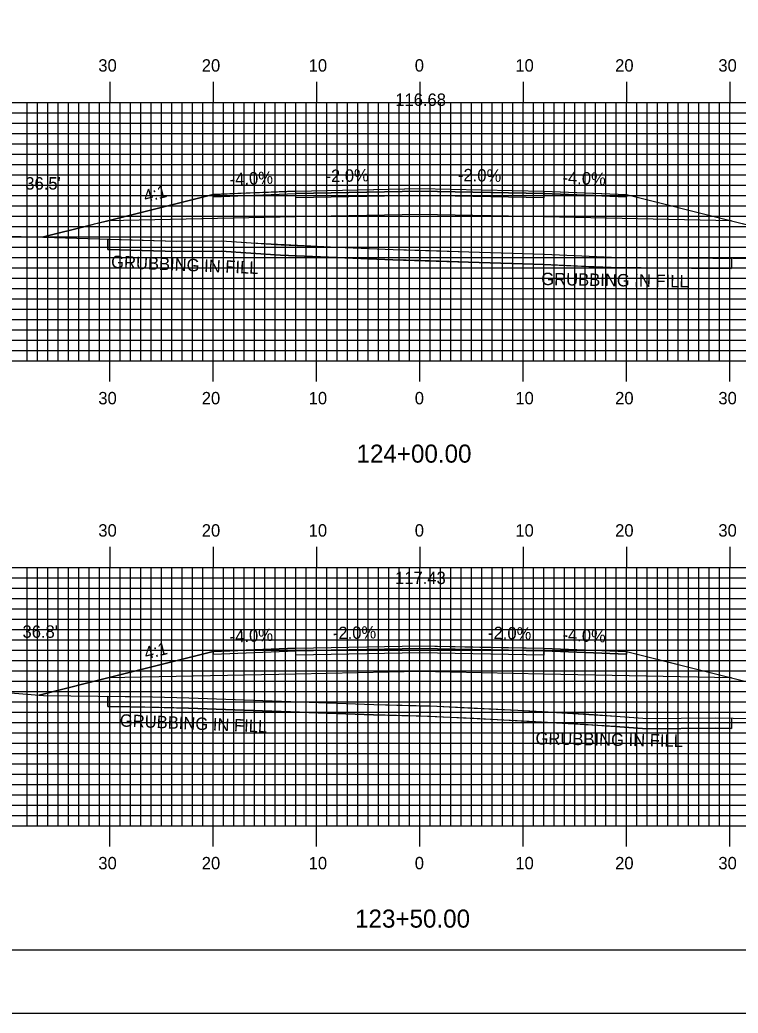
# Model space of a CAD drawing. Extents: x 1772809 to 1773153, y 442591 to 442811.
# Drawn here: x 1772936.4 to 1773005.9, y 442590.5 to 442686.7 of the extents above; entities that cross this region are included whole.
import ezdxf

# ---------------------------------------------------------------- set-up
doc = ezdxf.new("R2010")
doc.units = 0
for name, color, linetype in [('ANNOTATION', 7, 'Continuous'), ('BORDER', 7, 'Continuous'), ('D_Roadway_Centerline', 7, 'Continuous'), ('D_Roadway_Centerline_Text', 7, 'Continuous'), ('D_Roadway_Edge_Shoulder', 7, 'Continuous'), ('D_Roadway_Edge_TW', 7, 'Continuous'), ('D_Roadway_Pavement', 7, 'Continuous'), ('D_Roadway_SlopeLines', 7, 'Continuous'), ('D_Roadway_SubGrade', 7, 'Continuous'), ('D_Text_Standard', 7, 'Continuous'), ('GRUBBING IN FILL', 7, 'Continuous'), ('H_V ANNOTATION', 7, 'Continuous'), ('MAJOR', 7, 'Continuous'), ('MINOR', 7, 'Continuous'), ('PLOT BOUNDARY', 7, 'Continuous'), ('S_Roadway_Centerline', 7, 'Continuous')]:
    doc.layers.add(name, color=color, linetype=linetype)

msp = doc.modelspace()

# ---------------------------------------------------------------- linework, layer by layer
at = {"layer": 'BORDER'}
msp.add_lwpolyline([(1772825.52, 442596.665), (1773145.52, 442596.665), (1773145.52, 442806.665), (1772825.52, 442806.665)], close=True, dxfattribs=at)
at = {"layer": 'D_Roadway_Centerline'}
for points in [[(1772938.572, 442665.647), (1772943.119, 442666.784), (1772943.663, 442666.92), (1772944.946, 442667.24), (1772955.12, 442669.784), (1772957.831, 442669.893), (1772963.119, 442670.104), (1772973.69, 442670.316), (1772975.12, 442670.344), (1772987.119, 442670.104), (1772991.874, 442669.914), (1772995.12, 442669.784), (1773005.294, 442667.24), (1773009.361, 442666.224), (1773020.862, 442663.348)], [(1772938.304, 442621.329), (1772943.12, 442622.534), (1772944.93, 442622.986), (1772944.946, 442622.99), (1772945.075, 442623.022), (1772955.12, 442625.534), (1772963.12, 442625.854), (1772975.12, 442626.094), (1772980.946, 442625.978), (1772987.12, 442625.854), (1772995.119, 442625.534), (1773000.632, 442624.156), (1773005.293, 442622.99), (1773023.945, 442618.327)]]:
    msp.add_lwpolyline(points, dxfattribs=at)
at = {"layer": 'D_Roadway_Edge_Shoulder'}
for points in [[(1772963.119, 442670.104), (1772955.12, 442669.784), (1772955.12, 442669.534), (1772963.119, 442669.854)], [(1772987.119, 442670.104), (1772995.12, 442669.784), (1772995.12, 442669.534), (1772987.119, 442669.854)], [(1772963.12, 442625.854), (1772955.12, 442625.534), (1772955.12, 442625.284), (1772963.12, 442625.604)], [(1772987.12, 442625.854), (1772995.119, 442625.534), (1772995.119, 442625.284), (1772987.12, 442625.604)]]:
    msp.add_lwpolyline(points, close=True, dxfattribs=at)
at = {"layer": 'D_Roadway_Edge_TW'}
for points in [[(1772963.119, 442669.854), (1772963.119, 442670.104), (1772975.12, 442670.344), (1772987.119, 442670.104), (1772987.119, 442669.854), (1772975.12, 442670.094)], [(1772963.12, 442625.604), (1772963.12, 442625.854), (1772975.12, 442626.094), (1772987.12, 442625.854), (1772987.12, 442625.604), (1772975.12, 442625.844)]]:
    msp.add_lwpolyline(points, close=True, dxfattribs=at)
at = {"layer": 'D_Roadway_Pavement'}
for points in [[(1772963.119, 442669.437), (1772963.119, 442669.854), (1772975.12, 442670.094), (1772987.119, 442669.854), (1772987.119, 442669.437), (1772975.12, 442669.677)], [(1772963.12, 442625.187), (1772963.12, 442625.604), (1772975.12, 442625.844), (1772987.12, 442625.604), (1772987.12, 442625.187), (1772975.12, 442625.427)]]:
    msp.add_lwpolyline(points, close=True, dxfattribs=at)
at = {"layer": 'D_Roadway_SlopeLines'}
for points in [[(1772955.12, 442669.784), (1772944.946, 442667.24), (1772943.119, 442666.784), (1772938.572, 442665.647)], [(1772995.12, 442669.784), (1773005.294, 442667.24), (1773020.862, 442663.348)], [(1772955.12, 442625.534), (1772944.946, 442622.99), (1772943.12, 442622.534), (1772938.304, 442621.329)], [(1772995.119, 442625.534), (1773005.293, 442622.99), (1773023.945, 442618.327)]]:
    msp.add_lwpolyline(points, dxfattribs=at)
at = {"layer": 'D_Roadway_SubGrade'}
for points in [[(1772963.119, 442667.604), (1772944.946, 442667.24), (1772955.12, 442669.784), (1772955.12, 442669.534), (1772963.119, 442669.854), (1772975.12, 442670.094), (1772987.119, 442669.854), (1772995.12, 442669.534), (1772995.12, 442669.784), (1773005.294, 442667.24), (1772987.119, 442667.604), (1772975.12, 442667.844)], [(1772963.12, 442623.354), (1772944.946, 442622.99), (1772955.12, 442625.534), (1772955.12, 442625.284), (1772963.12, 442625.604), (1772975.12, 442625.844), (1772987.12, 442625.604), (1772995.119, 442625.284), (1772995.119, 442625.534), (1773005.293, 442622.99), (1772987.12, 442623.354), (1772975.12, 442623.594)]]:
    msp.add_lwpolyline(points, close=True, dxfattribs=at)
at = {"layer": 'GRUBBING IN FILL'}
for p, q in [((1772944.946, 442665.449), (1772944.946, 442664.448)), ((1772944.946, 442665.449), (1772944.946, 442664.448)), ((1773005.294, 442663.615), (1773005.294, 442662.615)), ((1773005.294, 442663.615), (1773005.294, 442662.615)), ((1772944.946, 442621.214), (1772944.946, 442620.214)), ((1772944.946, 442621.214), (1772944.946, 442620.214)), ((1773005.293, 442619.099), (1773005.293, 442618.099)), ((1773005.293, 442619.099), (1773005.293, 442618.099))]:
    msp.add_line(p, q, dxfattribs=at)
for points in [[(1772944.946, 442665.449), (1772951.585, 442665.243), (1772955.937, 442665.302), (1772958.821, 442665.109), (1772967.126, 442664.689), (1772972.546, 442664.462), (1772975.12, 442664.38), (1772975.12, 442663.38), (1772972.509, 442663.462), (1772967.08, 442663.69), (1772961.651, 442663.917), (1772955.91, 442664.301), (1772953.743, 442664.272), (1772951.576, 442664.242), (1772948.261, 442664.345), (1772944.946, 442664.448)], [(1772944.946, 442665.449), (1772951.585, 442665.243), (1772955.937, 442665.302), (1772958.821, 442665.109), (1772967.126, 442664.689), (1772972.546, 442664.462), (1772975.12, 442664.38), (1772975.12, 442663.38), (1772972.509, 442663.462), (1772967.08, 442663.69), (1772961.651, 442663.917), (1772955.91, 442664.301), (1772953.743, 442664.272), (1772951.576, 442664.242), (1772948.261, 442664.345), (1772944.946, 442664.448)], [(1772975.12, 442664.38), (1772979.865, 442664.231), (1772987.185, 442663.999), (1772993.671, 442663.693), (1773003.491, 442663.627), (1773005.294, 442663.615), (1773005.294, 442662.615), (1772999.469, 442662.654), (1772993.644, 442662.693), (1772990.395, 442662.847), (1772987.145, 442663), (1772979.827, 442663.231), (1772975.12, 442663.38)], [(1772975.12, 442664.38), (1772979.865, 442664.231), (1772987.185, 442663.999), (1772993.671, 442663.693), (1773003.491, 442663.627), (1773005.294, 442663.615), (1773005.294, 442662.615), (1772999.469, 442662.654), (1772993.644, 442662.693), (1772990.395, 442662.847), (1772987.145, 442663), (1772979.827, 442663.231), (1772975.12, 442663.38)], [(1772944.946, 442621.214), (1772949.251, 442621.157), (1772952.79, 442621.064), (1772961.732, 442620.742), (1772970.673, 442620.42), (1772975.12, 442620.302), (1772975.12, 442619.302), (1772970.642, 442619.421), (1772961.7, 442619.742), (1772952.758, 442620.064), (1772947.088, 442620.186), (1772944.946, 442620.214)], [(1772944.946, 442621.214), (1772949.251, 442621.157), (1772952.79, 442621.064), (1772961.732, 442620.742), (1772970.673, 442620.42), (1772975.12, 442620.302), (1772975.12, 442619.302), (1772970.642, 442619.421), (1772961.7, 442619.742), (1772952.758, 442620.064), (1772947.088, 442620.186), (1772944.946, 442620.214)], [(1772975.12, 442620.302), (1772976.166, 442620.275), (1772980.387, 442620.063), (1772984.607, 442619.852), (1772987.835, 442619.679), (1772994.102, 442619.289), (1772997.141, 442619.072), (1773003.711, 442619.13), (1773005.293, 442619.099), (1773005.293, 442618.099), (1773003.706, 442618.13), (1773000.408, 442618.101), (1772997.109, 442618.072), (1772994.055, 442618.29), (1772980.342, 442619.064), (1772975.12, 442619.302)], [(1772975.12, 442620.302), (1772976.166, 442620.275), (1772980.387, 442620.063), (1772984.607, 442619.852), (1772987.835, 442619.679), (1772994.102, 442619.289), (1772997.141, 442619.072), (1773003.711, 442619.13), (1773005.293, 442619.099), (1773005.293, 442618.099), (1773003.706, 442618.13), (1773000.408, 442618.101), (1772997.109, 442618.072), (1772994.055, 442618.29), (1772980.342, 442619.064), (1772975.12, 442619.302)]]:
    msp.add_lwpolyline(points, close=True, dxfattribs=at)
for points in [[(1772944.946, 442664.448), (1772951.576, 442664.242), (1772955.91, 442664.301), (1772961.651, 442663.917), (1772972.509, 442663.462), (1772987.145, 442663), (1772993.644, 442662.693), (1773005.294, 442662.615)], [(1772944.946, 442664.448), (1772951.576, 442664.242), (1772955.91, 442664.301), (1772961.651, 442663.917), (1772972.509, 442663.462), (1772987.145, 442663), (1772993.644, 442662.693), (1773005.294, 442662.615)], [(1772944.946, 442620.214), (1772949.231, 442620.158), (1772952.758, 442620.064), (1772970.642, 442619.421), (1772976.128, 442619.275), (1772984.555, 442618.853), (1772991, 442618.508), (1772997.109, 442618.072), (1773003.706, 442618.13), (1773005.293, 442618.099)], [(1772944.946, 442620.214), (1772949.231, 442620.158), (1772952.758, 442620.064), (1772970.642, 442619.421), (1772976.128, 442619.275), (1772984.555, 442618.853), (1772991, 442618.508), (1772997.109, 442618.072), (1773003.706, 442618.13), (1773005.293, 442618.099)]]:
    msp.add_lwpolyline(points, dxfattribs=at)
at = {"layer": 'MAJOR'}
for p, q in [((1772945.12, 442680.669), (1772945.12, 442678.665)), ((1772955.12, 442680.669), (1772955.12, 442678.665)), ((1772965.12, 442680.669), (1772965.12, 442678.665)), ((1772975.12, 442680.669), (1772975.12, 442678.665)), ((1772985.12, 442680.669), (1772985.12, 442678.665)), ((1772995.12, 442680.669), (1772995.12, 442678.665)), ((1773005.12, 442680.669), (1773005.12, 442678.665)), ((1772835.12, 442678.665), (1773115.12, 442678.665)), ((1772835.12, 442678.665), (1773115.12, 442678.665)), ((1772945.12, 442653.665), (1772945.12, 442678.665)), ((1772955.12, 442653.665), (1772955.12, 442678.665)), ((1772965.12, 442653.665), (1772965.12, 442678.665)), ((1772975.12, 442653.665), (1772975.12, 442678.665)), ((1772985.12, 442653.665), (1772985.12, 442678.665)), ((1772995.12, 442653.665), (1772995.12, 442678.665)), ((1773005.12, 442653.665), (1773005.12, 442678.665)), ((1772835.12, 442673.665), (1773115.12, 442673.665)), ((1772835.12, 442668.665), (1773115.12, 442668.665)), ((1772835.12, 442663.665), (1773115.12, 442663.665)), ((1772835.12, 442658.665), (1773115.12, 442658.665)), ((1772835.12, 442653.665), (1773115.12, 442653.665)), ((1772835.12, 442653.665), (1773115.12, 442653.665)), ((1772945.12, 442651.661), (1772945.12, 442653.665)), ((1772955.12, 442651.661), (1772955.12, 442653.665)), ((1772965.12, 442651.661), (1772965.12, 442653.665)), ((1772975.12, 442651.661), (1772975.12, 442653.665)), ((1772985.12, 442651.661), (1772985.12, 442653.665)), ((1772995.12, 442651.661), (1772995.12, 442653.665)), ((1773005.12, 442651.661), (1773005.12, 442653.665)), ((1772945.12, 442635.669), (1772945.12, 442633.665)), ((1772955.12, 442635.669), (1772955.12, 442633.665)), ((1772965.12, 442635.669), (1772965.12, 442633.665)), ((1772975.12, 442635.669), (1772975.12, 442633.665)), ((1772985.12, 442635.669), (1772985.12, 442633.665)), ((1772995.12, 442635.669), (1772995.12, 442633.665)), ((1773005.12, 442635.669), (1773005.12, 442633.665)), ((1772835.12, 442633.665), (1773115.12, 442633.665)), ((1772835.12, 442633.665), (1773115.12, 442633.665)), ((1772945.12, 442608.665), (1772945.12, 442633.665)), ((1772955.12, 442608.665), (1772955.12, 442633.665)), ((1772965.12, 442608.665), (1772965.12, 442633.665)), ((1772975.12, 442608.665), (1772975.12, 442633.665)), ((1772985.12, 442608.665), (1772985.12, 442633.665)), ((1772995.12, 442608.665), (1772995.12, 442633.665)), ((1773005.12, 442608.665), (1773005.12, 442633.665)), ((1772835.12, 442628.665), (1773115.12, 442628.665)), ((1772835.12, 442623.665), (1773115.12, 442623.665)), ((1772835.12, 442618.665), (1773115.12, 442618.665)), ((1772835.12, 442613.665), (1773115.12, 442613.665)), ((1772835.12, 442608.665), (1773115.12, 442608.665)), ((1772835.12, 442608.665), (1773115.12, 442608.665)), ((1772945.12, 442606.661), (1772945.12, 442608.665)), ((1772955.12, 442606.661), (1772955.12, 442608.665)), ((1772965.12, 442606.661), (1772965.12, 442608.665)), ((1772975.12, 442606.661), (1772975.12, 442608.665)), ((1772985.12, 442606.661), (1772985.12, 442608.665)), ((1772995.12, 442606.661), (1772995.12, 442608.665)), ((1773005.12, 442606.661), (1773005.12, 442608.665))]:
    msp.add_line(p, q, dxfattribs=at)
at = {"layer": 'MINOR'}
for p, q in [((1772937.12, 442653.665), (1772937.12, 442678.665)), ((1772938.12, 442653.665), (1772938.12, 442678.665)), ((1772939.12, 442653.665), (1772939.12, 442678.665)), ((1772940.12, 442653.665), (1772940.12, 442678.665)), ((1772941.12, 442653.665), (1772941.12, 442678.665)), ((1772942.12, 442653.665), (1772942.12, 442678.665)), ((1772943.12, 442653.665), (1772943.12, 442678.665)), ((1772944.12, 442653.665), (1772944.12, 442678.665)), ((1772946.12, 442653.665), (1772946.12, 442678.665)), ((1772947.12, 442653.665), (1772947.12, 442678.665)), ((1772948.12, 442653.665), (1772948.12, 442678.665)), ((1772949.12, 442653.665), (1772949.12, 442678.665)), ((1772950.12, 442653.665), (1772950.12, 442678.665)), ((1772951.12, 442653.665), (1772951.12, 442678.665)), ((1772952.12, 442653.665), (1772952.12, 442678.665)), ((1772953.12, 442653.665), (1772953.12, 442678.665)), ((1772954.12, 442653.665), (1772954.12, 442678.665)), ((1772956.12, 442653.665), (1772956.12, 442678.665)), ((1772957.12, 442653.665), (1772957.12, 442678.665)), ((1772958.12, 442653.665), (1772958.12, 442678.665)), ((1772959.12, 442653.665), (1772959.12, 442678.665)), ((1772960.12, 442653.665), (1772960.12, 442678.665)), ((1772961.12, 442653.665), (1772961.12, 442678.665)), ((1772962.12, 442653.665), (1772962.12, 442678.665)), ((1772963.12, 442653.665), (1772963.12, 442678.665)), ((1772964.12, 442653.665), (1772964.12, 442678.665)), ((1772966.12, 442653.665), (1772966.12, 442678.665)), ((1772967.12, 442653.665), (1772967.12, 442678.665)), ((1772968.12, 442653.665), (1772968.12, 442678.665)), ((1772969.12, 442653.665), (1772969.12, 442678.665)), ((1772970.12, 442653.665), (1772970.12, 442678.665)), ((1772971.12, 442653.665), (1772971.12, 442678.665)), ((1772972.12, 442653.665), (1772972.12, 442678.665)), ((1772973.12, 442653.665), (1772973.12, 442678.665)), ((1772974.12, 442653.665), (1772974.12, 442678.665)), ((1772976.12, 442653.665), (1772976.12, 442678.665)), ((1772977.12, 442653.665), (1772977.12, 442678.665)), ((1772978.12, 442653.665), (1772978.12, 442678.665)), ((1772979.12, 442653.665), (1772979.12, 442678.665)), ((1772980.12, 442653.665), (1772980.12, 442678.665)), ((1772981.12, 442653.665), (1772981.12, 442678.665)), ((1772982.12, 442653.665), (1772982.12, 442678.665)), ((1772983.12, 442653.665), (1772983.12, 442678.665)), ((1772984.12, 442653.665), (1772984.12, 442678.665)), ((1772986.12, 442653.665), (1772986.12, 442678.665)), ((1772987.12, 442653.665), (1772987.12, 442678.665)), ((1772988.12, 442653.665), (1772988.12, 442678.665)), ((1772989.12, 442653.665), (1772989.12, 442678.665)), ((1772990.12, 442653.665), (1772990.12, 442678.665)), ((1772991.12, 442653.665), (1772991.12, 442678.665)), ((1772992.12, 442653.665), (1772992.12, 442678.665)), ((1772993.12, 442653.665), (1772993.12, 442678.665)), ((1772994.12, 442653.665), (1772994.12, 442678.665)), ((1772996.12, 442653.665), (1772996.12, 442678.665)), ((1772997.12, 442653.665), (1772997.12, 442678.665)), ((1772998.12, 442653.665), (1772998.12, 442678.665)), ((1772999.12, 442653.665), (1772999.12, 442678.665)), ((1773000.12, 442653.665), (1773000.12, 442678.665)), ((1773001.12, 442653.665), (1773001.12, 442678.665)), ((1773002.12, 442653.665), (1773002.12, 442678.665)), ((1773003.12, 442653.665), (1773003.12, 442678.665)), ((1773004.12, 442653.665), (1773004.12, 442678.665)), ((1772835.12, 442677.665), (1773115.12, 442677.665)), ((1772835.12, 442676.665), (1773115.12, 442676.665)), ((1772835.12, 442675.665), (1773115.12, 442675.665)), ((1772835.12, 442674.665), (1773115.12, 442674.665)), ((1772835.12, 442672.665), (1773115.12, 442672.665)), ((1772835.12, 442671.665), (1773115.12, 442671.665)), ((1772835.12, 442670.665), (1773115.12, 442670.665)), ((1772835.12, 442669.665), (1773115.12, 442669.665)), ((1772835.12, 442667.665), (1773115.12, 442667.665)), ((1772835.12, 442666.665), (1773115.12, 442666.665)), ((1772835.12, 442665.665), (1773115.12, 442665.665)), ((1772835.12, 442664.665), (1773115.12, 442664.665)), ((1772835.12, 442662.665), (1773115.12, 442662.665)), ((1772835.12, 442661.665), (1773115.12, 442661.665)), ((1772835.12, 442660.665), (1773115.12, 442660.665)), ((1772835.12, 442659.665), (1773115.12, 442659.665)), ((1772835.12, 442657.665), (1773115.12, 442657.665)), ((1772835.12, 442656.665), (1773115.12, 442656.665)), ((1772835.12, 442655.665), (1773115.12, 442655.665)), ((1772835.12, 442654.665), (1773115.12, 442654.665)), ((1772937.12, 442608.665), (1772937.12, 442633.665)), ((1772938.12, 442608.665), (1772938.12, 442633.665)), ((1772939.12, 442608.665), (1772939.12, 442633.665)), ((1772940.12, 442608.665), (1772940.12, 442633.665)), ((1772941.12, 442608.665), (1772941.12, 442633.665)), ((1772942.12, 442608.665), (1772942.12, 442633.665)), ((1772943.12, 442608.665), (1772943.12, 442633.665)), ((1772944.12, 442608.665), (1772944.12, 442633.665)), ((1772946.12, 442608.665), (1772946.12, 442633.665)), ((1772947.12, 442608.665), (1772947.12, 442633.665)), ((1772948.12, 442608.665), (1772948.12, 442633.665)), ((1772949.12, 442608.665), (1772949.12, 442633.665)), ((1772950.12, 442608.665), (1772950.12, 442633.665)), ((1772951.12, 442608.665), (1772951.12, 442633.665)), ((1772952.12, 442608.665), (1772952.12, 442633.665)), ((1772953.12, 442608.665), (1772953.12, 442633.665)), ((1772954.12, 442608.665), (1772954.12, 442633.665)), ((1772956.12, 442608.665), (1772956.12, 442633.665)), ((1772957.12, 442608.665), (1772957.12, 442633.665)), ((1772958.12, 442608.665), (1772958.12, 442633.665)), ((1772959.12, 442608.665), (1772959.12, 442633.665)), ((1772960.12, 442608.665), (1772960.12, 442633.665)), ((1772961.12, 442608.665), (1772961.12, 442633.665)), ((1772962.12, 442608.665), (1772962.12, 442633.665)), ((1772963.12, 442608.665), (1772963.12, 442633.665)), ((1772964.12, 442608.665), (1772964.12, 442633.665)), ((1772966.12, 442608.665), (1772966.12, 442633.665)), ((1772967.12, 442608.665), (1772967.12, 442633.665)), ((1772968.12, 442608.665), (1772968.12, 442633.665)), ((1772969.12, 442608.665), (1772969.12, 442633.665)), ((1772970.12, 442608.665), (1772970.12, 442633.665)), ((1772971.12, 442608.665), (1772971.12, 442633.665)), ((1772972.12, 442608.665), (1772972.12, 442633.665)), ((1772973.12, 442608.665), (1772973.12, 442633.665)), ((1772974.12, 442608.665), (1772974.12, 442633.665)), ((1772976.12, 442608.665), (1772976.12, 442633.665)), ((1772977.12, 442608.665), (1772977.12, 442633.665)), ((1772978.12, 442608.665), (1772978.12, 442633.665)), ((1772979.12, 442608.665), (1772979.12, 442633.665)), ((1772980.12, 442608.665), (1772980.12, 442633.665)), ((1772981.12, 442608.665), (1772981.12, 442633.665)), ((1772982.12, 442608.665), (1772982.12, 442633.665)), ((1772983.12, 442608.665), (1772983.12, 442633.665)), ((1772984.12, 442608.665), (1772984.12, 442633.665)), ((1772986.12, 442608.665), (1772986.12, 442633.665)), ((1772987.12, 442608.665), (1772987.12, 442633.665)), ((1772988.12, 442608.665), (1772988.12, 442633.665)), ((1772989.12, 442608.665), (1772989.12, 442633.665)), ((1772990.12, 442608.665), (1772990.12, 442633.665)), ((1772991.12, 442608.665), (1772991.12, 442633.665)), ((1772992.12, 442608.665), (1772992.12, 442633.665)), ((1772993.12, 442608.665), (1772993.12, 442633.665)), ((1772994.12, 442608.665), (1772994.12, 442633.665)), ((1772996.12, 442608.665), (1772996.12, 442633.665)), ((1772997.12, 442608.665), (1772997.12, 442633.665)), ((1772998.12, 442608.665), (1772998.12, 442633.665)), ((1772999.12, 442608.665), (1772999.12, 442633.665)), ((1773000.12, 442608.665), (1773000.12, 442633.665)), ((1773001.12, 442608.665), (1773001.12, 442633.665)), ((1773002.12, 442608.665), (1773002.12, 442633.665)), ((1773003.12, 442608.665), (1773003.12, 442633.665)), ((1773004.12, 442608.665), (1773004.12, 442633.665)), ((1772835.12, 442632.665), (1773115.12, 442632.665)), ((1772835.12, 442631.665), (1773115.12, 442631.665)), ((1772835.12, 442630.665), (1773115.12, 442630.665)), ((1772835.12, 442629.665), (1773115.12, 442629.665)), ((1772835.12, 442627.665), (1773115.12, 442627.665)), ((1772835.12, 442626.665), (1773115.12, 442626.665)), ((1772835.12, 442625.665), (1773115.12, 442625.665)), ((1772835.12, 442624.665), (1773115.12, 442624.665)), ((1772835.12, 442622.665), (1773115.12, 442622.665)), ((1772835.12, 442621.665), (1773115.12, 442621.665)), ((1772835.12, 442620.665), (1773115.12, 442620.665)), ((1772835.12, 442619.665), (1773115.12, 442619.665)), ((1772835.12, 442617.665), (1773115.12, 442617.665)), ((1772835.12, 442616.665), (1773115.12, 442616.665)), ((1772835.12, 442615.665), (1773115.12, 442615.665)), ((1772835.12, 442614.665), (1773115.12, 442614.665)), ((1772835.12, 442612.665), (1773115.12, 442612.665)), ((1772835.12, 442611.665), (1773115.12, 442611.665)), ((1772835.12, 442610.665), (1773115.12, 442610.665)), ((1772835.12, 442609.665), (1773115.12, 442609.665))]:
    msp.add_line(p, q, dxfattribs=at)
at = {"layer": 'PLOT BOUNDARY'}
msp.add_lwpolyline([(1772809.333, 442590.547), (1773149.333, 442590.547), (1773149.333, 442810.547), (1772809.333, 442810.547)], close=True, dxfattribs=at)
at = {"layer": 'S_Roadway_Centerline'}
for points in [[(1772935.479, 442665.743), (1772951.585, 442665.243), (1772955.937, 442665.302), (1772961.706, 442664.916), (1772972.546, 442664.462), (1772987.185, 442663.999), (1772993.671, 442663.693), (1773013.311, 442663.562), (1773014.292, 442663.564), (1773015.021, 442663.567), (1773021.733, 442663.315), (1773035.371, 442662.832), (1773038.833, 442662.712), (1773048.314, 442662.47), (1773056.216, 442662.376), (1773064.83, 442662.134), (1773071.035, 442661.858), (1773090.084, 442661.486), (1773094.75, 442661.414), (1773098.702, 442661.369), (1773107.812, 442661.006), (1773115.12, 442660.898)], [(1772927.491, 442622.198), (1772938.723, 442621.296), (1772949.251, 442621.157), (1772952.79, 442621.064), (1772970.673, 442620.42), (1772976.166, 442620.275), (1772984.607, 442619.852), (1772991.062, 442619.506), (1772997.141, 442619.072), (1773003.711, 442619.13), (1773012.346, 442618.962), (1773019.706, 442618.544), (1773029.253, 442618.057), (1773032.005, 442617.966), (1773033.837, 442617.907), (1773044.639, 442617.715)]]:
    msp.add_lwpolyline(points, dxfattribs=at)

# ---------------------------------------------------------------- texts
at = {"layer": 'ANNOTATION'}
for s, rotation, p in [('-4.0%', 2.29082, (1772956.751, 442670.651)), ('-2.0%', 1.1457, (1772966.011, 442670.962)), ('-2.0%', 358.85416, (1772978.806, 442671.071)), ('-4.0%', 357.70959, (1772988.911, 442670.834)), ('4:1', 14.03876, (1772948.568, 442669.008)), ('-4.0%', 2.29063, (1772956.752, 442626.401)), ('-2.0%', 1.14577, (1772966.726, 442626.727)), ('-2.0%', 358.85423, (1772981.719, 442626.763)), ('-4.0%', 357.70937, (1772988.911, 442626.584)), ('4:1', 14.03924, (1772948.633, 442624.774))]:
    msp.add_text(s, height=1.2, rotation=rotation, dxfattribs=at).set_placement(p)
at = {"layer": 'D_Roadway_Centerline'}
for s, p in [('C', (1772975.115, 442670.344)), ('L', (1772975.12, 442670.337)), ('C', (1772975.114, 442626.094)), ('L', (1772975.12, 442626.087))]:
    msp.add_text(s, height=0.0146, dxfattribs=at).set_placement(p)
at = {"layer": 'D_Roadway_Centerline_Text'}
for s, p in [('116.68', (1772972.75, 442678.348)), ('117.43', (1772972.728, 442632.072))]:
    msp.add_text(s, height=1.2, dxfattribs=at).set_placement(p)
at = {"layer": 'D_Text_Standard'}
for s, p in [("36.5'", (1772936.952, 442670.251)), ("36.8'", (1772936.681, 442626.872))]:
    msp.add_text(s, height=1.2, dxfattribs=at).set_placement(p)
at = {"layer": 'GRUBBING IN FILL'}
for rotation, p in [(357.57187, (1772945.235, 442662.679)), (359.01917, (1772986.871, 442661.015)), (357.57187, (1772946.077, 442618.292)), (359.01917, (1772986.316, 442616.549))]:
    msp.add_text('GRUBBING IN FILL', height=1.2, rotation=rotation, dxfattribs=at).set_placement(p)
at = {"layer": 'H_V ANNOTATION'}
for s, height, p in [('30', 1.2, (1772944.017, 442681.665)), ('20', 1.2, (1772954.028, 442681.665)), ('10', 1.2, (1772964.37, 442681.665)), ('0', 1.2, (1772974.638, 442681.665)), ('10', 1.2, (1772984.37, 442681.665)), ('20', 1.2, (1772994.028, 442681.665)), ('30', 1.2, (1773004.017, 442681.665)), ('30', 1.2, (1772944.017, 442649.465)), ('20', 1.2, (1772954.028, 442649.465)), ('10', 1.2, (1772964.37, 442649.465)), ('0', 1.2, (1772974.638, 442649.465)), ('10', 1.2, (1772984.37, 442649.465)), ('20', 1.2, (1772994.028, 442649.465)), ('30', 1.2, (1773004.017, 442649.465)), ('124+00.00', 1.75, (1772969.002, 442643.821)), ('30', 1.2, (1772944.017, 442636.665)), ('20', 1.2, (1772954.028, 442636.665)), ('10', 1.2, (1772964.37, 442636.665)), ('0', 1.2, (1772974.638, 442636.665)), ('10', 1.2, (1772984.37, 442636.665)), ('20', 1.2, (1772994.028, 442636.665)), ('30', 1.2, (1773004.017, 442636.665)), ('30', 1.2, (1772944.017, 442604.465)), ('20', 1.2, (1772954.028, 442604.465)), ('10', 1.2, (1772964.37, 442604.465)), ('0', 1.2, (1772974.638, 442604.465)), ('10', 1.2, (1772984.37, 442604.465)), ('20', 1.2, (1772994.028, 442604.465)), ('30', 1.2, (1773004.017, 442604.465)), ('123+50.00', 1.75, (1772968.862, 442598.821))]:
    msp.add_text(s, height=height, dxfattribs=at).set_placement(p)

doc.saveas('drawing.dxf')
